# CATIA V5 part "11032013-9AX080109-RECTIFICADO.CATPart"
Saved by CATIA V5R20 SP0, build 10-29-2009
Part number: 11032013-9AX080109-RECTIFICADO
Revision: ANY
Definition: UNKNOWN
Nomenclature: 11032013-9AX080109-RECTIFICADO
Source: Unknown
Bounding box of the stored display mesh (mm): x -4 to 4, y -3.804 to 4, z -54.5 to 54.5
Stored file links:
  C:\Users\Utente\Desktop\IO LAVORO\3D X SITO CF\CUMSA\3D files CX.013058\CX 013058\11032013-9AX080109-RECTIFICADO.CATPart
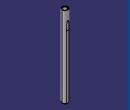
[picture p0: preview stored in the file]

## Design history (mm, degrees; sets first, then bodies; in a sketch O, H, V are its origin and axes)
Body1 "Cortar-Extruir-Lámina2" (main body)
  Solid1: solid without history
